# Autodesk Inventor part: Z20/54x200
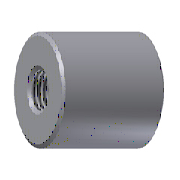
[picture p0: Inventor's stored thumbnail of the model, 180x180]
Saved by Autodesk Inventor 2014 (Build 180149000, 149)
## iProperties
IsCustomPart: 0
Created: 2009-11
Part Number: Z20/54x200
Material: DIN 1.2312
Description: Locating sleeves
Document SubType Name: Modeling
Designer: gaom
Standard Revision: 1
Manufacturer: HASCO
Language: en-US
Size Designation: 54x200
Categories: <MemberInstance><Categories><Category DisplayName="Mold" InternalName="349578f2-f4d4-4954-8c09-8e99297a61c0" Mnemonic="MOLD"><Category DisplayName="Locatings" I
Mass: 1.68626 g
Surface Area: 16.3679 cm^2
Volume: 1.68626 cm^3
Density: 7.85 g/cm^3
Appearance: Anodized - Dark Gray
Author: gaom
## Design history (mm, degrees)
sketch "Sketch1"
  geometry: L1 (0, -240)-(0, 40) reference; L2 (0, 0)-(27, 0); L3 (27, 0)-(27, -4.5); L4 (27, -4.5)-(26.986, -4.5); L5 (26.986, -4.5)-(26.986, -200); L6 (26.986, -200)-(21.5, -200); L7 (21.5, -200)-(21.5, -13); L8 (21.5, -13)-(10, -11); L9 (10, -11)-(0, -11); L10 (0, 0)-(0, -11); 1 further point
  constraints: 18 end point, 4 parallel, 3 perpendicular, 2 point on line, 1 coincident, 1 collinear
  dimensions: "d0" = 54 diameter of L3 L1 (= D); "d2" = 54 dimension on L5 L1 (= D_Guide); "d4" = 200 distance between parallel lines of L6 L2 (= L); "d5" = 43 diameter of L7 L1 (= d_); "d6" = 13 distance from line of L7.end L2 (= L1); "d7" = 2 distance from line of L7.end L9; "d8" = 20 diameter of L8.end L1 (= M); "d33" = 4.5 distance between parallel lines of L2 L4 (= L2)
revolve "Revolution1" sketch "Sketch1" stored, may be unused: angle "d9" = 90 deg
sketch "Sketch2"
  geometry: 1 further point
hole "Hole1" sketch "Sketch2" at (0, 0) diameter "d10" = 17.294; stored, may be unused: countersink angle "d14" = 90 deg, drill point angle "d16" = 0 deg; dims "d11" = 6, "d12" = 4, "d13" = 2, "d15" = 200 (= L)
chamfer "Chamfer1" distance "d17" = 0.5; stored, may be unused: second distance "d18" = 2, angle "d19" = 45 deg
fillet "Fillet1" dims "d30" = 0.5
body "Solid1"
other parameters: "D" = 54 [user parameter; used in 1 equation term], "L" = 200 [user parameter; used in 2 equation terms], "d_" = 43 [user parameter; used in 1 equation term], "M" = 20 [user parameter; used in 1 equation term], "L1" = 13 [user parameter; used in 1 equation term], "d22" = 0, "D_Guide" = 54 [user parameter; used in 1 equation term], "d31" = 0, "d32" = 0, "L2" = 4.5 [user parameter; used in 1 equation term]
